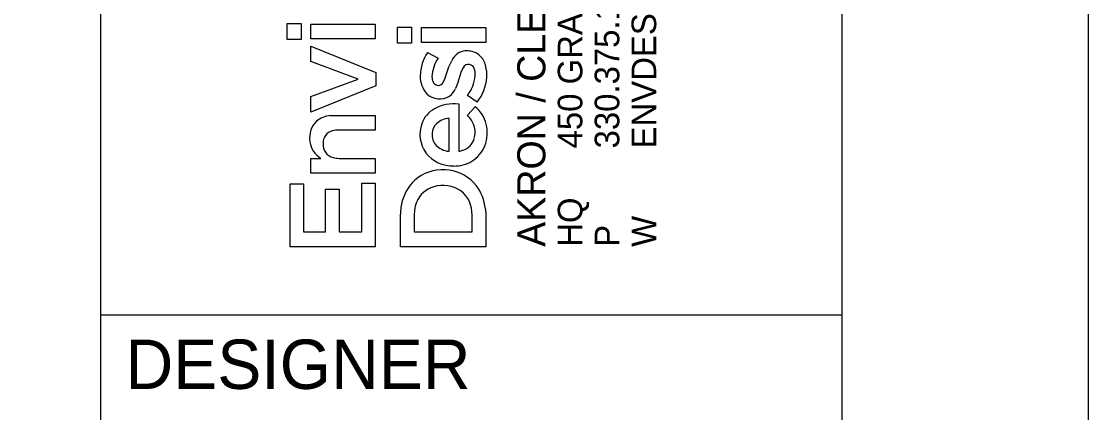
# Model space of a CAD drawing. Extents: x -0.6 to 34, y 0 to 22.
# Drawn here: x 31.839 to 34, y 2.302 to 3.095 of the extents above; entities that cross this region are included whole.
import ezdxf

# ---------------------------------------------------------------- set-up
doc = ezdxf.new("R2010")
doc.units = 0
for name, color, linetype in [('SH_Border', 7, 'Continuous'), ('SH_Cut_Line', 7, 'Continuous'), ('SH_Data', 7, 'Continuous')]:
    doc.layers.add(name, color=color, linetype=linetype)

msp = doc.modelspace()

# ---------------------------------------------------------------- linework, layer by layer
at = {"layer": 'SH_Border'}
msp.add_lwpolyline([(0, 0), (34, 0), (34, 22), (0, 22)], close=True, dxfattribs=at)
at = {"layer": 'SH_Cut_Line'}
for p, q in [((32.3771, 3.0582), (32.3771, 3.0903)), ((32.3771, 3.0903), (32.4054, 3.0903)), ((32.4054, 3.0903), (32.4054, 3.0582)), ((32.4254, 3.0594), (32.4254, 3.0893)), ((32.4254, 3.0893), (32.5557, 3.0893)), ((32.5557, 3.0893), (32.5557, 3.0594)), ((32.6005, 3.0511), (32.6005, 3.0832)), ((32.6005, 3.0832), (32.6289, 3.0832)), ((32.6289, 3.0832), (32.6289, 3.0511)), ((32.6489, 3.0523), (32.6489, 3.0822)), ((32.6489, 3.0822), (32.7792, 3.0822)), ((32.7792, 3.0822), (32.7792, 3.0523)), ((32.4054, 3.0582), (32.3771, 3.0582)), ((32.5557, 3.0594), (32.4254, 3.0594)), ((32.6289, 3.0511), (32.6005, 3.0511)), ((32.7792, 3.0523), (32.6489, 3.0523)), ((32.4254, 3.0133), (32.4254, 3.0446)), ((32.4254, 3.0446), (32.5567, 2.9913)), ((32.6615, 3.0321), (32.6827, 3.0203)), ((32.5212, 2.978), (32.4254, 3.0133)), ((32.7048, 3.0026), (32.7104, 3.0153)), ((32.5567, 2.9913), (32.5567, 2.9644)), ((32.6967, 2.9787), (32.7048, 3.0026)), ((32.7298, 2.9933), (32.7221, 2.9688)), ((32.7334, 3.001), (32.7298, 2.9933)), ((32.4254, 2.9429), (32.5212, 2.978)), ((32.5567, 2.9644), (32.4254, 2.9109)), ((32.693, 2.9712), (32.6967, 2.9787)), ((32.7221, 2.9688), (32.7182, 2.9592)), ((32.4254, 2.9109), (32.4254, 2.9429)), ((32.7621, 2.9314), (32.742, 2.9447)), ((32.7245, 2.9275), (32.7246, 2.8319)), ((32.7423, 2.9046), (32.7577, 2.922)), ((32.4644, 2.904), (32.4729, 2.9044)), ((32.4729, 2.9044), (32.5557, 2.9044)), ((32.5557, 2.9044), (32.5557, 2.8746)), ((32.7049, 2.8318), (32.7049, 2.8983)), ((32.5557, 2.8746), (32.4814, 2.8746)), ((32.7036, 2.8317), (32.7049, 2.8318)), ((32.4254, 2.7875), (32.4254, 2.8173)), ((32.4254, 2.8173), (32.4455, 2.8173)), ((32.4822, 2.8173), (32.5557, 2.8173)), ((32.5557, 2.8173), (32.5557, 2.7876)), ((32.5557, 2.7876), (32.4254, 2.7875)), ((32.5286, 2.6683), (32.5286, 2.7672)), ((32.5286, 2.7672), (32.5557, 2.7672)), ((32.5557, 2.7672), (32.5557, 2.6379)), ((32.383, 2.6379), (32.383, 2.766)), ((32.383, 2.766), (32.4101, 2.766)), ((32.4101, 2.766), (32.4101, 2.6683)), ((32.455, 2.6683), (32.455, 2.7549)), ((32.455, 2.7549), (32.4822, 2.7549)), ((32.4822, 2.7549), (32.4822, 2.6683)), ((32.6064, 2.638), (32.6064, 2.704)), ((32.6347, 2.7118), (32.6341, 2.7023)), ((32.6341, 2.7023), (32.6341, 2.6684)), ((32.7515, 2.6683), (32.7515, 2.7024)), ((32.7785, 2.715), (32.7792, 2.7021)), ((32.7792, 2.7021), (32.7792, 2.638)), ((32.4101, 2.6683), (32.455, 2.6683)), ((32.4822, 2.6683), (32.5286, 2.6683)), ((32.6341, 2.6684), (32.7515, 2.6683)), ((32.5557, 2.6379), (32.383, 2.6379)), ((32.7792, 2.638), (32.6064, 2.638))]:
    msp.add_line(p, q, dxfattribs=at)
for points in [[(32.3771, 3.0582), (32.3771, 3.0903), (32.4054, 3.0903), (32.4054, 3.0582)], [(32.4254, 3.0594), (32.4254, 3.0893), (32.5557, 3.0893), (32.5557, 3.0594)], [(32.6005, 3.0511), (32.6005, 3.0832), (32.6289, 3.0832), (32.6289, 3.0511)], [(32.6489, 3.0523), (32.6489, 3.0822), (32.7792, 3.0822), (32.7792, 3.0523)], [(32.4254, 2.9109), (32.4254, 2.9429), (32.5212, 2.978), (32.4254, 3.0133), (32.4254, 3.0446), (32.5567, 2.9913), (32.5567, 2.9644)], [(32.383, 2.6379), (32.383, 2.766), (32.4101, 2.766), (32.4101, 2.6683), (32.455, 2.6683), (32.455, 2.7549), (32.4822, 2.7549), (32.4822, 2.6683), (32.5286, 2.6683), (32.5286, 2.7672), (32.5557, 2.7672), (32.5557, 2.6379)]]:
    msp.add_lwpolyline(points, close=True, dxfattribs=at)
for points in [[(32.6615, 3.0321), (32.6827, 3.0203)], [(32.693, 2.9712), (32.6967, 2.9787), (32.7048, 3.0026), (32.7104, 3.0153)], [(32.7334, 3.001), (32.7298, 2.9933), (32.7221, 2.9688), (32.7182, 2.9592)], [(32.7621, 2.9314), (32.742, 2.9447)], [(32.7245, 2.9275), (32.7246, 2.8319)], [(32.7423, 2.9046), (32.7577, 2.922)], [(32.4644, 2.904), (32.4729, 2.9044), (32.5557, 2.9044), (32.5557, 2.8746), (32.4814, 2.8746)], [(32.7036, 2.8317), (32.7049, 2.8318), (32.7049, 2.8983)], [(32.4254, 2.7875), (32.4254, 2.8173), (32.4455, 2.8173)], [(32.4822, 2.8173), (32.5557, 2.8173), (32.5557, 2.7876), (32.4254, 2.7875)], [(32.7785, 2.715), (32.7792, 2.7021), (32.7792, 2.638), (32.6064, 2.638)], [(32.6064, 2.638), (32.6064, 2.704)], [(32.6347, 2.7118), (32.6341, 2.7023), (32.6341, 2.6684), (32.7515, 2.6683), (32.7515, 2.7024)]]:
    msp.add_lwpolyline(points, dxfattribs=at)
for centre, radius, start, end in [((32.7364, 2.9826), 0.0897, 146.531, 178.7571), ((32.7364, 2.9826), 0.0897, 146.531, 178.7571), ((32.7466, 2.9971), 0.0405, 125.5118, 153.4159), ((32.7466, 2.9971), 0.0405, 125.5118, 153.4159), ((32.7406, 3.0026), 0.0326, 80.1719, 122.5197), ((32.7406, 3.0026), 0.0326, 80.1719, 122.5197), ((32.7428, 2.9982), 0.0367, 47.7934, 84.6892), ((32.7428, 2.9982), 0.0367, 47.7934, 84.6892), ((32.7452, 2.9789), 0.0749, 146.5112, 176.9101), ((32.7452, 2.9789), 0.0749, 146.5112, 176.9101), ((32.7438, 2.9963), 0.0114, 76.6609, 155.7053), ((32.7438, 2.9963), 0.0114, 76.6609, 155.7053), ((32.744, 2.9951), 0.0126, 21.5098, 78.5262), ((32.744, 2.9951), 0.0126, 21.5098, 78.5262), ((32.7379, 2.9946), 0.0427, 14.9966, 46.2063), ((32.7379, 2.9946), 0.0427, 14.9966, 46.2063), ((32.7104, 2.9867), 0.0712, 355.8306, 15.3914), ((32.7104, 2.9867), 0.0712, 355.8306, 15.3914), ((32.6967, 2.9824), 0.0501, 177.5366, 222.7932), ((32.6967, 2.9824), 0.0501, 177.5366, 222.7932), ((32.6931, 2.9823), 0.0228, 178.4747, 211.0868), ((32.6931, 2.9823), 0.0228, 178.4747, 211.0868), ((32.6825, 2.9915), 0.0757, 321.811, 354.7969), ((32.6825, 2.9915), 0.0757, 321.811, 354.7969), ((32.7259, 2.9877), 0.0321, 354.5726, 22.068), ((32.7259, 2.9877), 0.0321, 354.5726, 22.068), ((32.6833, 2.9767), 0.0115, 212.2368, 268.3777), ((32.6833, 2.9767), 0.0115, 212.2368, 268.3777), ((32.6834, 2.9759), 0.0107, 267.716, 333.7337), ((32.6834, 2.9759), 0.0107, 267.716, 333.7337), ((32.6895, 2.9882), 0.0922, 321.9777, 355.8738), ((32.6895, 2.9882), 0.0922, 321.9777, 355.8738), ((32.686, 2.9753), 0.0375, 225.9854, 302.4797), ((32.686, 2.9753), 0.0375, 225.9854, 302.4797), ((32.681, 2.9758), 0.0408, 308.0877, 335.9874), ((32.681, 2.9758), 0.0408, 308.0877, 335.9874), ((32.7024, 2.8691), 0.0558, 118.8308, 160.6244), ((32.7024, 2.8691), 0.0558, 118.8308, 160.6244), ((32.7152, 2.8441), 0.0838, 83.615, 118.2876), ((32.7152, 2.8441), 0.0838, 83.615, 118.2876), ((32.7174, 2.8717), 0.0644, 13.5336, 51.3615), ((32.7174, 2.8717), 0.0644, 13.5336, 51.3615), ((32.4687, 2.8543), 0.0499, 94.9696, 130.2225), ((32.4687, 2.8543), 0.0499, 94.9696, 130.2225), ((32.7079, 2.8561), 0.0424, 94.008, 130.8817), ((32.7079, 2.8561), 0.0424, 94.008, 130.8817), ((32.7038, 2.8656), 0.0549, 19.0357, 45.4406), ((32.7038, 2.8656), 0.0549, 19.0357, 45.4406), ((32.4787, 2.8582), 0.056, 162.2736, 187.7919), ((32.4787, 2.8582), 0.056, 162.2736, 187.7919), ((32.4635, 2.8626), 0.0402, 132.2219, 161.6818), ((32.4635, 2.8626), 0.0402, 132.2219, 161.6818), ((32.4811, 2.8286), 0.046, 89.6049, 105.3284), ((32.4811, 2.8286), 0.046, 89.6049, 105.3284), ((32.7104, 2.8661), 0.0644, 160.5201, 215.7831), ((32.7104, 2.8661), 0.0644, 160.5201, 215.7831), ((32.7005, 2.8663), 0.0298, 132.9851, 177.179), ((32.7005, 2.8663), 0.0298, 132.9851, 177.179), ((32.7107, 2.8697), 0.047, 344.6059, 17.007), ((32.7107, 2.8697), 0.047, 344.6059, 17.007), ((32.7064, 2.8692), 0.0758, 339.3542, 13.3785), ((32.7064, 2.8692), 0.0758, 339.3542, 13.3785), ((32.4748, 2.8487), 0.025, 103.6865, 182.2187), ((32.4748, 2.8487), 0.025, 103.6865, 182.2187), ((32.7017, 2.865), 0.0311, 175.0013, 223.283), ((32.7017, 2.865), 0.0311, 175.0013, 223.283), ((32.7224, 2.8671), 0.035, 288.0077, 343.5508), ((32.7224, 2.8671), 0.035, 288.0077, 343.5508), ((32.4703, 2.858), 0.0476, 188.962, 238.7037), ((32.4703, 2.858), 0.0476, 188.962, 238.7037), ((32.4773, 2.8456), 0.0276, 175.5854, 255.1439), ((32.4773, 2.8456), 0.0276, 175.5854, 255.1439), ((32.7089, 2.8736), 0.0423, 225.0619, 262.7974), ((32.7089, 2.8736), 0.0423, 225.0619, 262.7974), ((32.7247, 2.8522), 0.0202, 269.7003, 294.8711), ((32.7247, 2.8522), 0.0202, 269.7003, 294.8711), ((32.7189, 2.8652), 0.0626, 300.9427, 338.7323), ((32.7189, 2.8652), 0.0626, 300.9427, 338.7323), ((32.4818, 2.8595), 0.0422, 254.0916, 270.5284), ((32.4818, 2.8595), 0.0422, 254.0916, 270.5284), ((32.7125, 2.8705), 0.0687, 217.7452, 271.6543), ((32.7125, 2.8705), 0.0687, 217.7452, 271.6543), ((32.7155, 2.8724), 0.0706, 269.2048, 300.3341), ((32.7155, 2.8724), 0.0706, 269.2048, 300.3341), ((32.6923, 2.7079), 0.0864, 81.194, 125.9984), ((32.6923, 2.7079), 0.0864, 81.194, 125.9984), ((32.6946, 2.7113), 0.0827, 37.8521, 82.402), ((32.6946, 2.7113), 0.0827, 37.8521, 82.402), ((32.6939, 2.7089), 0.0865, 127.2362, 165.148), ((32.6939, 2.7089), 0.0865, 127.2362, 165.148), ((32.6889, 2.7078), 0.054, 106.1881, 157.3861), ((32.6889, 2.7078), 0.054, 106.1881, 157.3861), ((32.6928, 2.6986), 0.0639, 55.6727, 107.2093), ((32.6928, 2.6986), 0.0639, 55.6727, 107.2093), ((32.6929, 2.705), 0.0587, 357.4662, 52.2665), ((32.6929, 2.705), 0.0587, 357.4662, 52.2665), ((32.6859, 2.7057), 0.0931, 5.7333, 37.304), ((32.6859, 2.7057), 0.0931, 5.7333, 37.304), ((32.7143, 2.7028), 0.1078, 164.7861, 179.3704), ((32.7143, 2.7028), 0.1078, 164.7861, 179.3704), ((32.6983, 2.7039), 0.0641, 157.3571, 172.9275), ((32.6983, 2.7039), 0.0641, 157.3571, 172.9275)]:
    msp.add_arc(centre, radius, start, end, dxfattribs=at)
at = {"layer": 'SH_Data'}
for p, q in [((32, 0.5), (32, 21.5)), ((32, 2.5), (33.5, 2.5))]:
    msp.add_line(p, q, dxfattribs=at)
msp.add_lwpolyline([(1.5, 21.5), (33.5, 21.5), (33.5, 0.5), (1.5, 0.5)], close=True, dxfattribs=at)

# ---------------------------------------------------------------- texts
at = {"layer": 'SH_Cut_Line'}
for s, height, p in [('450 GRANT ST., AKRON, OH  44311', 0.049846, (32.9749, 2.8374)), ('AKRON / CLEVELAND / COLUMBUS', 0.056969, (32.9001, 2.638)), ('ENVDESIGNGROUP.COM', 0.049846, (33.1244, 2.8374)), ('330.375.1390', 0.049846, (33.0497, 2.8374)), ('HQ ', 0.04985, (32.9749, 2.638)), ('W', 0.0498, (33.1244, 2.638)), ('P', 0.0498, (33.0497, 2.638))]:
    msp.add_text(s, height=height, rotation=90, dxfattribs=at).set_placement(p)
msp.add_text('DESIGNER', height=0.1, dxfattribs=at).set_placement((32.05, 2.35))

doc.saveas('drawing.dxf')
